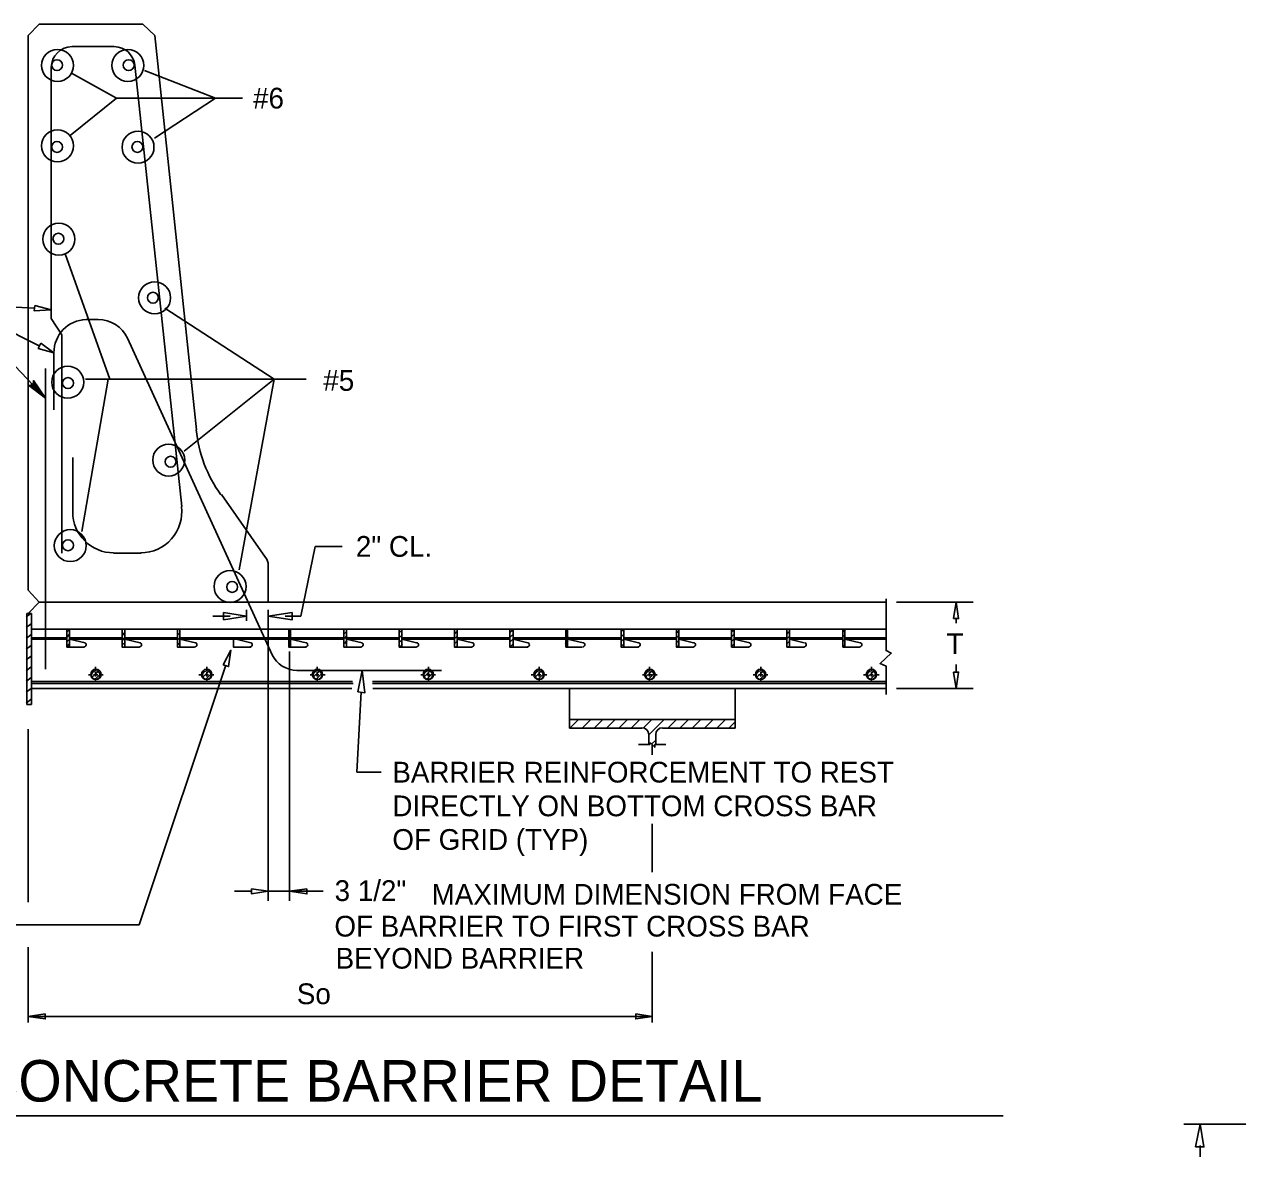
# Model space of a CAD drawing. Extents: x -24512 to -22484, y 4569 to 6351.
# Drawn here: x -24064.8 to -23889.5, y 6061.6 to 6225.3 of the extents above; entities that cross this region are included whole.
import ezdxf

# ---------------------------------------------------------------- set-up
doc = ezdxf.new("R2010")
doc.units = 0
for name, color, linetype in [('10', 7, 'Continuous'), ('11', 7, 'Continuous'), ('4', 7, 'Continuous'), ('5', 7, 'Continuous'), ('8', 7, 'Continuous'), ('PLT-BNDY', 7, 'Continuous')]:
    doc.layers.add(name, color=color, linetype=linetype)

# ---------------------------------------------------------------- blocks, each defined once
blk = doc.blocks.new('JUQ000')
at = {"layer": '4'}
for p, q in [((71.0975, 21.771125), (71.421875, 22.095625)), ((71.237875, 21.6265), (71.566625, 21.95525))]:
    blk.add_line(p, q, dxfattribs=at)
blk = doc.blocks.new('JUQ001')
at = {"layer": '4'}
for p, q in [((66.419125, 24.506), (66.4355, 24.522375)), ((66.419125, 24.220875), (66.570375, 24.372125)), ((66.419125, 23.93575), (66.570375, 24.087)), ((66.419125, 23.650625), (66.570375, 23.801875)), ((66.567875, 23.514375), (66.570375, 23.51675))]:
    blk.add_line(p, q, dxfattribs=at)
blk = doc.blocks.new('_X')
at = {"layer": '4'}
for p, q in [((63.193375, 24.416625), (63.299125, 24.522375)), ((63.193375, 24.1315), (63.3445, 24.282625)), ((63.193375, 23.846375), (63.3445, 23.9975)), ((63.193375, 23.56125), (63.3445, 23.712375))]:
    blk.add_line(p, q, dxfattribs=at)
blk = doc.blocks.new('JUQ002')
at = {"layer": '4'}
for p, q in [((72.87075, 24.39975), (72.993375, 24.522375)), ((72.87075, 24.114625), (73.021875, 24.265875)), ((72.87075, 23.8295), (73.021875, 23.98075)), ((72.87075, 23.544375), (73.021875, 23.695625))]:
    blk.add_line(p, q, dxfattribs=at)
blk = doc.blocks.new('JUQ003')
at = {"layer": '4'}
for p, q in [((89.35625, 63.69525), (89.860375, 64.19925)), ((90.069125, 63.69525), (90.573125, 64.19925)), ((90.781875, 63.69525), (91.285875, 64.19925)), ((91.49475, 63.69525), (91.99875, 64.19925)), ((92.2075, 63.69525), (92.7115, 64.19925)), ((92.920375, 63.69525), (93.424375, 64.19925)), ((93.628875, 63.691), (94.137125, 64.19925)), ((93.972625, 63.321875), (94.85, 64.19925)), ((95.05875, 63.69525), (95.56275, 64.19925)), ((95.7715, 63.69525), (96.275625, 64.19925)), ((96.484375, 63.69525), (96.988375, 64.19925)), ((97.197125, 63.69525), (97.70125, 64.19925)), ((97.91, 63.69525), (98.414, 64.19925)), ((98.62275, 63.69525), (99.014, 64.0865)), ((94.121125, 62.757625), (94.377, 63.013375))]:
    blk.add_line(p, q, dxfattribs=at)
blk = doc.blocks.new('JUQ004')
at = {"layer": '4'}
for p, q in [((69.644875, 24.310375), (69.796125, 24.4615)), ((69.644875, 24.02525), (69.796125, 24.176375)), ((69.644875, 23.740125), (69.796125, 23.89125)), ((69.70425, 23.514375), (69.796125, 23.60625))]:
    blk.add_line(p, q, dxfattribs=at)

msp = doc.modelspace()

# ---------------------------------------------------------------- linework, layer by layer
at = {"layer": '10'}
for p, q in [((-24037.18, 6214.64), (-24047.44, 6218.63)), ((-24051.5, 6214.64), (-24057.97, 6218.26)), ((-24051.5, 6214.64), (-24058.15, 6209.22)), ((-24051.5, 6214.64), (-24033.29, 6214.64)), ((-24037.18, 6214.64), (-24045.97, 6208.85)), ((-24058.88, 6192.15), (-24052.44, 6174.03)), ((-24062.64, 6178.84), (-24074.73, 6184.92)), ((-24063.38, 6184.3), (-24074.73, 6184.92)), ((-24061.72, 6171.26), (-24074.73, 6184.92)), ((-24044.49, 6184.3), (-24028.7, 6174.03)), ((-24055.88, 6182.64), (-24054.14, 6182.64)), ((-24052.7, 6174.03), (-24056.49, 6151.99)), ((-24055.93, 6174.03), (-24024.06, 6174.03)), ((-24028.7, 6174.03), (-24041.72, 6163.62)), ((-24028.7, 6174.03), (-24033.78, 6146.45)), ((-24024.85, 6139.78), (-24022.78, 6149.84)), ((-24022.78, 6149.84), (-24018.89, 6149.84)), ((-23938.82, 6141.78), (-23927.72, 6141.78)), ((-24035.08, 6139.78), (-24037.57, 6139.78)), ((-24032.71, 6140.67), (-24032.71, 6139.1)), ((-24029.59, 6140.67), (-24029.59, 6098.64)), ((-24027.1, 6139.78), (-24024.85, 6139.78)), ((-23930.21, 6138.78), (-23930.21, 6139.41)), ((-24026.47, 6134.67), (-24026.47, 6098.64)), ((-24035.7, 6132.67), (-24048.21, 6095.14)), ((-23930.21, 6131.68), (-23930.21, 6132.8)), ((-24055.03, 6131.3), (-24055.52, 6131.3)), ((-24054.15, 6131.3), (-24054.78, 6131.3)), ((-24054.53, 6131.93), (-24054.53, 6132.43)), ((-24054.53, 6131.05), (-24054.53, 6131.68)), ((-24053.4, 6131.3), (-24053.9, 6131.3)), ((-24039.07, 6131.3), (-24039.56, 6131.3)), ((-24038.19, 6131.3), (-24038.69, 6131.3)), ((-24038.44, 6131.93), (-24038.44, 6132.43)), ((-24038.44, 6131.05), (-24038.44, 6131.68)), ((-24037.44, 6131.3), (-24037.82, 6131.3)), ((-24022.98, 6131.3), (-24023.48, 6131.3)), ((-24022.23, 6131.3), (-24022.73, 6131.3)), ((-24022.48, 6131.93), (-24022.48, 6132.43)), ((-24022.48, 6131.05), (-24022.48, 6131.68)), ((-24021.36, 6131.3), (-24021.86, 6131.3)), ((-24007.02, 6131.3), (-24007.52, 6131.3)), ((-24006.15, 6131.3), (-24006.65, 6131.3)), ((-24006.4, 6131.93), (-24006.4, 6132.43)), ((-24006.4, 6131.05), (-24006.4, 6131.68)), ((-24005.4, 6131.3), (-24005.9, 6131.3)), ((-23991.06, 6131.3), (-23991.56, 6131.3)), ((-23990.19, 6131.3), (-23990.69, 6131.3)), ((-23990.44, 6131.93), (-23990.44, 6132.43)), ((-23990.44, 6131.05), (-23990.44, 6131.68)), ((-23989.32, 6131.3), (-23989.94, 6131.3)), ((-23974.98, 6131.3), (-23975.48, 6131.3)), ((-23974.1, 6131.3), (-23974.73, 6131.3)), ((-23974.48, 6131.93), (-23974.48, 6132.43)), ((-23974.48, 6131.05), (-23974.48, 6131.68)), ((-23973.36, 6131.3), (-23973.85, 6131.3)), ((-23959.02, 6131.3), (-23959.52, 6131.3)), ((-23958.14, 6131.3), (-23958.77, 6131.3)), ((-23958.39, 6131.93), (-23958.39, 6132.43)), ((-23958.39, 6131.05), (-23958.39, 6131.68)), ((-23957.4, 6131.3), (-23957.89, 6131.3)), ((-23942.93, 6131.3), (-23943.56, 6131.3)), ((-23942.18, 6131.3), (-23942.68, 6131.3)), ((-23942.43, 6131.93), (-23942.43, 6132.43)), ((-23942.43, 6131.05), (-23942.43, 6131.68)), ((-23941.31, 6131.3), (-23941.81, 6131.3)), ((-24054.53, 6130.31), (-24054.53, 6130.8)), ((-24038.44, 6130.31), (-24038.44, 6130.8)), ((-24022.48, 6130.31), (-24022.48, 6130.8)), ((-24006.4, 6130.31), (-24006.4, 6130.8)), ((-23990.44, 6130.31), (-23990.44, 6130.8)), ((-23974.48, 6130.31), (-23974.48, 6130.8)), ((-23958.39, 6130.31), (-23958.39, 6130.8)), ((-23942.43, 6130.31), (-23942.43, 6130.8)), ((-23938.82, 6129.31), (-23927.72, 6129.31)), ((-24016.12, 6128.81), (-24016.75, 6117.21)), ((-24064.25, 6123.45), (-24064.25, 6098.43)), ((-23974.1, 6121.2), (-23974.1, 6119.71)), ((-24016.75, 6117.21), (-24013.26, 6117.21)), ((-23974.1, 6109.73), (-23974.1, 6102.75)), ((-24031.96, 6100.01), (-24034.45, 6100.01)), ((-24029.59, 6100.01), (-24021.61, 6100.01)), ((-24048.21, 6095.14), (-24078.1, 6095.14)), ((-24064.25, 6091.91), (-24064.25, 6081.05)), ((-23974.1, 6091.23), (-23974.1, 6081.05)), ((-24064.25, 6081.93), (-23974.1, 6081.93)), ((-23886.34, 6066.37), (-23897.31, 6066.37)), ((-23894.94, 6063.26), (-23894.94, 6061.64))]:
    msp.add_line(p, q, dxfattribs=at)
for points in [[(-24063.26, 6184.67), (-24063.38, 6183.92), (-24060.89, 6184.05)], [(-24062.39, 6179.21), (-24062.77, 6178.46), (-24060.52, 6177.84)], [(-23930.59, 6139.41), (-23929.84, 6139.41), (-23930.21, 6141.78)], [(-24036.02, 6140.31), (-24036.02, 6139.26), (-24032.71, 6139.78)], [(-24026.1, 6140.31), (-24026.1, 6139.26), (-24029.59, 6139.78)], [(-24036.09, 6132.73), (-24035.29, 6132.49), (-24034.94, 6134.83)], [(-24016.62, 6128.81), (-24015.62, 6128.68), (-24016, 6131.93)], [(-23930.59, 6131.68), (-23929.84, 6131.68), (-23930.21, 6129.31)], [(-24031.96, 6100.38), (-24031.96, 6099.63), (-24029.59, 6100.01)], [(-24023.98, 6100.38), (-24023.98, 6099.63), (-24026.47, 6100.01)], [(-24061.76, 6082.3), (-24061.76, 6081.55), (-24064.25, 6081.93)], [(-23976.47, 6082.3), (-23976.47, 6081.55), (-23974.1, 6081.93)], [(-23895.64, 6063.06), (-23894.42, 6063.06), (-23894.94, 6066.37)]]:
    msp.add_lwpolyline(points, close=True, dxfattribs=at)
msp.add_lwpolyline([(-24063.45, 6173.62), (-24063.53, 6173.4), (-24061.72, 6171.26), (-24063.45, 6173.62), (-24063.46, 6173.81), (-24061.72, 6171.26), (-24063.74, 6173.19), (-24063.96, 6173.13), (-24061.72, 6171.26), (-24064.17, 6173.14), (-24063.96, 6173.13)], dxfattribs=at)
for centre in [(-24060, 6219.37), (-24049.84, 6219.37), (-24060, 6207.74), (-24048.37, 6207.55), (-24059.81, 6194.26), (-24045.97, 6185.77), (-24058.52, 6173.59), (-24043.94, 6162.33), (-24058.15, 6149.96), (-24035.08, 6144.06)]:
    msp.add_circle(centre, 2.31, dxfattribs=at)
for centre, radius, start, end in [((-24057.89, 6219.08), 3, 90, 180), ((-24051.81, 6219.08), 3, 6.0542, 90), ((-24055.72, 6177.84), 4.8, 91.8539, 180), ((-24054.18, 6177.84), 4.8, 26.0753, 89.5289), ((-24025.41, 6135.93), 4, 206.0754, 270)]:
    msp.add_arc(centre, radius, start, end, dxfattribs=at)
at = {"layer": '11'}
msp.add_line((-23923.43, 6067.54), (-24109.65, 6067.54), dxfattribs=at)
at = {"layer": '4'}
for p, q in [((-24064.51, 6139.66), (-24063.81, 6140.21)), ((-24064.51, 6138.11), (-24063.81, 6138.66)), ((-24064.51, 6136.55), (-24063.81, 6137.1)), ((-24064.51, 6134.99), (-24063.81, 6135.54)), ((-24064.51, 6133.44), (-24063.81, 6133.99)), ((-24064.51, 6131.88), (-24063.81, 6132.43)), ((-24064.51, 6130.33), (-24063.81, 6130.88)), ((-24064.51, 6128.77), (-24063.81, 6129.32)), ((-24064.51, 6127.21), (-24063.81, 6127.76))]:
    msp.add_line(p, q, dxfattribs=at)
at = {"layer": '5'}
for p, q in [((-24029.59, 6141.78), (-23940.31, 6141.78)), ((-24063.75, 6140.16), (-24064.45, 6140.16)), ((-24064.45, 6140.16), (-24064.45, 6126.99)), ((-24063.75, 6126.99), (-24063.75, 6140.16)), ((-24063.75, 6137.91), (-24058.64, 6137.91)), ((-24063.75, 6136.66), (-24058.64, 6136.66)), ((-24063.75, 6136.42), (-24058.64, 6136.42)), ((-24058.27, 6137.91), (-24050.66, 6137.91)), ((-24058.27, 6136.66), (-24050.66, 6136.66)), ((-24058.27, 6136.42), (-24050.66, 6136.42)), ((-24056.02, 6135.92), (-24058.27, 6136.42)), ((-24050.29, 6137.91), (-24042.68, 6137.91)), ((-24050.29, 6136.66), (-24042.68, 6136.66)), ((-24050.29, 6136.42), (-24042.68, 6136.42)), ((-24048.04, 6135.92), (-24050.29, 6136.42)), ((-24042.31, 6137.91), (-24034.58, 6137.91)), ((-24042.31, 6136.66), (-24034.58, 6136.66)), ((-24042.31, 6136.42), (-24034.58, 6136.42)), ((-24040.06, 6135.92), (-24042.31, 6136.42)), ((-24034.58, 6137.91), (-24026.6, 6137.91)), ((-24034.58, 6136.66), (-24026.6, 6136.66)), ((-24034.58, 6136.42), (-24026.6, 6136.42)), ((-24032.08, 6135.92), (-24034.2, 6136.42)), ((-24026.35, 6137.91), (-24018.62, 6137.91)), ((-24026.35, 6136.66), (-24018.62, 6136.66)), ((-24026.35, 6136.42), (-24018.62, 6136.42)), ((-24024.1, 6135.92), (-24026.35, 6136.42)), ((-24018.24, 6137.91), (-24010.64, 6137.91)), ((-24018.24, 6136.66), (-24010.64, 6136.66)), ((-24018.24, 6136.42), (-24010.64, 6136.42)), ((-24016, 6135.92), (-24018.24, 6136.42)), ((-24010.26, 6137.91), (-24002.66, 6137.91)), ((-24010.26, 6136.66), (-24002.66, 6136.66)), ((-24010.26, 6136.42), (-24002.66, 6136.42)), ((-24008.14, 6135.92), (-24010.26, 6136.42)), ((-24002.28, 6137.91), (-23994.68, 6137.91)), ((-24002.28, 6136.66), (-23994.68, 6136.66)), ((-24002.28, 6136.42), (-23994.68, 6136.42)), ((-24000.04, 6135.92), (-24002.28, 6136.42)), ((-23994.18, 6137.91), (-23986.57, 6137.91)), ((-23994.18, 6136.66), (-23986.57, 6136.66)), ((-23994.18, 6136.42), (-23986.57, 6136.42)), ((-23992.06, 6135.92), (-23994.18, 6136.42)), ((-23986.32, 6137.91), (-23978.59, 6137.91)), ((-23986.32, 6136.66), (-23978.59, 6136.66)), ((-23986.32, 6136.42), (-23978.59, 6136.42)), ((-23984.08, 6135.92), (-23986.32, 6136.42)), ((-23978.22, 6137.91), (-23970.61, 6137.91)), ((-23978.22, 6136.66), (-23970.61, 6136.66)), ((-23978.22, 6136.42), (-23970.61, 6136.42)), ((-23976.1, 6135.92), (-23978.22, 6136.42)), ((-23970.24, 6137.91), (-23962.63, 6137.91)), ((-23970.24, 6136.66), (-23962.63, 6136.66)), ((-23970.24, 6136.42), (-23962.63, 6136.42)), ((-23968.12, 6135.92), (-23970.24, 6136.42)), ((-23962.26, 6137.91), (-23954.65, 6137.91)), ((-23962.26, 6136.66), (-23954.65, 6136.66)), ((-23962.26, 6136.42), (-23954.65, 6136.42)), ((-23960.01, 6135.92), (-23962.26, 6136.42)), ((-23954.28, 6137.91), (-23946.55, 6137.91)), ((-23954.28, 6136.66), (-23946.55, 6136.66)), ((-23954.28, 6136.42), (-23946.55, 6136.42)), ((-23952.16, 6135.92), (-23954.28, 6136.42)), ((-23946.3, 6137.91), (-23940.31, 6137.91)), ((-23946.3, 6136.66), (-23940.31, 6136.66)), ((-23946.3, 6136.42), (-23940.31, 6136.42)), ((-23944.05, 6135.92), (-23946.3, 6136.42)), ((-24058.27, 6135.29), (-24056.15, 6135.29)), ((-24050.29, 6135.29), (-24048.17, 6135.29)), ((-24042.31, 6135.29), (-24040.19, 6135.29)), ((-24034.2, 6135.29), (-24032.08, 6135.29)), ((-24026.35, 6135.29), (-24024.1, 6135.29)), ((-24018.24, 6135.29), (-24016.12, 6135.29)), ((-24010.26, 6135.29), (-24008.14, 6135.29)), ((-24002.28, 6135.29), (-24000.16, 6135.29)), ((-23994.18, 6135.29), (-23992.06, 6135.29)), ((-23986.32, 6135.29), (-23984.2, 6135.29)), ((-23978.22, 6135.29), (-23976.1, 6135.29)), ((-23970.24, 6135.29), (-23968.12, 6135.29)), ((-23962.26, 6135.29), (-23960.14, 6135.29)), ((-23954.28, 6135.29), (-23952.16, 6135.29)), ((-23946.3, 6135.29), (-23944.18, 6135.29)), ((-24063.75, 6130.31), (-24017.39, 6130.31)), ((-24063.75, 6130.06), (-24017.29, 6130.06)), ((-24063.75, 6129.31), (-24017.48, 6129.31)), ((-24014.52, 6130.31), (-23940.31, 6130.31)), ((-24014.52, 6130.06), (-23940.31, 6130.06)), ((-24014.43, 6129.31), (-23940.31, 6129.31)), ((-23986.07, 6124.82), (-23986.07, 6129.31)), ((-23962.13, 6124.82), (-23962.13, 6129.31)), ((-24064.45, 6126.99), (-24063.75, 6126.99)), ((-23986.07, 6123.57), (-23986.07, 6124.82)), ((-23986.07, 6124.82), (-23962.13, 6124.82)), ((-23962.13, 6124.82), (-23962.13, 6123.57)), ((-23975.6, 6123.57), (-23986.07, 6123.57)), ((-23974.6, 6121.2), (-23974.6, 6122.7)), ((-23973.6, 6122.7), (-23973.6, 6121.2)), ((-23962.13, 6123.57), (-23972.61, 6123.57)), ((-23976.1, 6121.2), (-23974.6, 6121.2)), ((-23973.6, 6121.2), (-23972.11, 6121.2))]:
    msp.add_line(p, q, dxfattribs=at)
for points in [[(-23940.31, 6128.44), (-23940.31, 6132.55), (-23941.19, 6132.92), (-23939.57, 6134.42), (-23940.31, 6134.79), (-23940.31, 6142.28)], [(-24034.2, 6135.29), (-24034.58, 6135.29), (-24034.58, 6136.42)], [(-23974.6, 6121.2), (-23974.48, 6121.2), (-23974.35, 6121.45), (-23973.73, 6120.83), (-23973.73, 6121.2), (-23973.6, 6121.2)]]:
    msp.add_lwpolyline(points, dxfattribs=at)
for points in [[(-24058.27, 6137.91), (-24058.27, 6135.29), (-24058.64, 6135.29), (-24058.64, 6137.91)], [(-24050.29, 6137.91), (-24050.29, 6135.29), (-24050.66, 6135.29), (-24050.66, 6137.91)], [(-24042.31, 6137.91), (-24042.31, 6135.29), (-24042.68, 6135.29), (-24042.68, 6137.91)], [(-24026.35, 6137.91), (-24026.35, 6135.29), (-24026.6, 6135.29), (-24026.6, 6137.91)], [(-24018.24, 6137.91), (-24018.24, 6135.29), (-24018.62, 6135.29), (-24018.62, 6137.91)], [(-24010.26, 6137.91), (-24010.26, 6135.29), (-24010.64, 6135.29), (-24010.64, 6137.91)], [(-24002.28, 6137.91), (-24002.28, 6135.29), (-24002.66, 6135.29), (-24002.66, 6137.91)], [(-23994.18, 6137.91), (-23994.18, 6135.29), (-23994.68, 6135.29), (-23994.68, 6137.91)], [(-23986.32, 6137.91), (-23986.32, 6135.29), (-23986.57, 6135.29), (-23986.57, 6137.91)], [(-23978.22, 6137.91), (-23978.22, 6135.29), (-23978.59, 6135.29), (-23978.59, 6137.91)], [(-23970.24, 6137.91), (-23970.24, 6135.29), (-23970.61, 6135.29), (-23970.61, 6137.91)], [(-23962.26, 6137.91), (-23962.26, 6135.29), (-23962.63, 6135.29), (-23962.63, 6137.91)], [(-23954.28, 6137.91), (-23954.28, 6135.29), (-23954.65, 6135.29), (-23954.65, 6137.91)], [(-23946.3, 6137.91), (-23946.3, 6135.29), (-23946.55, 6135.29), (-23946.55, 6137.91)]]:
    msp.add_lwpolyline(points, close=True, dxfattribs=at)
for centre, radius in [((-24054.45, 6131.35), 0.75), ((-24054.45, 6131.23), 0.625), ((-24038.45, 6131.35), 0.75), ((-24038.45, 6131.23), 0.625), ((-24022.45, 6131.35), 0.75), ((-24022.45, 6131.23), 0.625), ((-24006.44, 6131.35), 0.75), ((-24006.44, 6131.23), 0.625), ((-23990.44, 6131.35), 0.75), ((-23990.44, 6131.23), 0.625), ((-23974.44, 6131.35), 0.75), ((-23974.44, 6131.23), 0.625), ((-23958.44, 6131.35), 0.75), ((-23958.44, 6131.23), 0.625), ((-23942.43, 6131.35), 0.75), ((-23942.43, 6131.23), 0.625)]:
    msp.add_circle(centre, radius, dxfattribs=at)
for centre, radius, start, end in [((-24056.16, 6135.64), 0.305, 271.249, 76.5605), ((-24048.16, 6135.64), 0.305, 271.249, 76.5605), ((-24040.16, 6135.64), 0.305, 271.249, 76.5605), ((-24032.16, 6135.64), 0.305, 271.249, 76.5605), ((-24024.16, 6135.64), 0.305, 271.249, 76.5605), ((-24016.16, 6135.64), 0.305, 271.249, 76.5605), ((-24008.15, 6135.64), 0.305, 271.249, 76.5605), ((-24000.15, 6135.64), 0.305, 271.249, 76.5605), ((-23992.15, 6135.64), 0.305, 271.249, 76.5605), ((-23984.15, 6135.64), 0.305, 271.249, 76.5605), ((-23976.15, 6135.64), 0.305, 271.249, 76.5605), ((-23968.15, 6135.64), 0.305, 271.249, 76.5605), ((-23960.15, 6135.64), 0.305, 271.249, 76.5605), ((-23952.15, 6135.64), 0.305, 271.249, 76.5605), ((-23944.14, 6135.64), 0.305, 271.249, 76.5605), ((-23975.59, 6122.64), 1, 0, 90), ((-23972.59, 6122.64), 1, 90, 180)]:
    msp.add_arc(centre, radius, start, end, dxfattribs=at)
at = {"layer": '8'}
for p, q in [((-24057.89, 6222.08), (-24051.81, 6222.08)), ((-24060.89, 6182.8), (-24060.89, 6219.08)), ((-24048.82, 6219.39), (-24042.06, 6155.62)), ((-24059.39, 6148.88), (-24059.39, 6179.56)), ((-24029.01, 6134.17), (-24049.87, 6179.95)), ((-24060.52, 6177.84), (-24060.52, 6169.58)), ((-24061.74, 6132.1), (-24061.72, 6175.56)), ((-24057.77, 6154.74), (-24057.77, 6162.72)), ((-24047.92, 6148.88), (-24051.91, 6148.88)), ((-24004.53, 6131.93), (-24025.41, 6131.93))]:
    msp.add_line(p, q, dxfattribs=at)
msp.add_lwpolyline([(-24059.39, 6179.56), (-24059.39, 6180.43), (-24060.89, 6182.8)], dxfattribs=at)
for centre in [(-24060.06, 6219.41), (-24049.72, 6219.41), (-24060.06, 6207.59), (-24048.45, 6207.59), (-24059.87, 6194.32), (-24046.22, 6185.79), (-24058.48, 6173.46), (-24043.66, 6162.09), (-24058.48, 6150.02), (-24034.77, 6144)]:
    msp.add_circle(centre, 0.788, dxfattribs=at)
for centre, start, end in [((-24047.96, 6154.83), 270, 7.4397), ((-24051.89, 6154.83), 180, 270)]:
    msp.add_arc(centre, 5.91, start, end, dxfattribs=at)
at = {"layer": 'PLT-BNDY'}
for p, q in [((-24064.25, 6223.7), (-24062.63, 6225.32)), ((-24047.67, 6225.32), (-24062.63, 6225.32)), ((-24045.92, 6223.7), (-24047.67, 6225.32)), ((-24064.25, 6223.7), (-24064.25, 6143.52)), ((-24045.92, 6223.7), (-24039.94, 6166.71)), ((-24036.32, 6157.36), (-24029.96, 6148.26)), ((-24029.59, 6147.14), (-24029.59, 6141.78)), ((-24064.25, 6143.52), (-24062.63, 6141.78)), ((-24064.25, 6140.16), (-24062.63, 6141.78)), ((-24029.59, 6141.78), (-24062.63, 6141.78))]:
    msp.add_line(p, q, dxfattribs=at)
for centre, radius, start, end in [((-24020.38, 6168.74), 19.69, 185.9906, 215.5377), ((-24031.54, 6147.11), 1.97, 0, 35.5377)]:
    msp.add_arc(centre, radius, start, end, dxfattribs=at)

# ---------------------------------------------------------------- block references
at = {"layer": '4', "xscale": 2.4803976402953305, "yscale": 2.4803976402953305}
for name, p in [('_X', (-24215.37, 6076.94)), ('JUQ001', (-24215.37, 6076.94)), ('JUQ001', (-24207.39, 6076.94)), ('JUQ002', (-24207.39, 6076.94)), ('JUQ004', (-24191.31, 6076.94)), ('JUQ002', (-24191.31, 6076.94)), ('JUQ004', (-24175.35, 6076.94)), ('JUQ002', (-24175.35, 6076.94)), ('JUQ004', (-24159.39, 6076.94)), ('JUQ002', (-24159.39, 6076.94)), ('JUQ004', (-24143.43, 6076.94)), ('JUQ002', (-24143.43, 6076.94)), ('JUQ004', (-24127.34, 6076.94)), ('JUQ002', (-24127.34, 6076.94)), ('JUQ000', (-24231.33, 6076.94)), ('JUQ000', (-24215.37, 6076.94)), ('JUQ000', (-24199.41, 6076.94)), ('JUQ000', (-24183.45, 6076.94)), ('JUQ000', (-24167.37, 6076.94)), ('JUQ000', (-24151.41, 6076.94)), ('JUQ000', (-24135.32, 6076.94)), ('JUQ000', (-24119.36, 6076.94)), ('JUQ003', (-24207.64, 5965.59))]:
    msp.add_blockref(name, p, dxfattribs=at)

# ---------------------------------------------------------------- texts
at = {"layer": '10'}
for s, p in [('#6', (-24031.75, 6213.14)), ('#5', (-24021.6, 6172.34)), ('2" CL.', (-24016.9, 6148.35)), ('T', (-23931.59, 6134.28)), ('BARRIER REINFORCEMENT TO REST ', (-24011.63, 6115.72)), ('DIRECTLY ON BOTTOM CROSS BAR ', (-24011.63, 6110.85)), ('OF GRID (TYP)', (-24011.63, 6105.99)), ('3 1/2"', (-24019.97, 6098.6)), ('MAXIMUM DIMENSION FROM FACE ', (-24005.96, 6098.07)), ('OF BARRIER TO FIRST CROSS BAR ', (-24020, 6093.46)), ('BEYOND BARRIER', (-24019.83, 6088.83)), ('So', (-24025.43, 6083.69))]:
    msp.add_text(s, height=3, dxfattribs=at).set_placement(p)
at = {"layer": '11'}
msp.add_text('TYPICAL CONCRETE BARRIER DETAIL', height=6.0008, dxfattribs=at).set_placement((-24107.11, 6069.61))

doc.saveas('drawing.dxf')
